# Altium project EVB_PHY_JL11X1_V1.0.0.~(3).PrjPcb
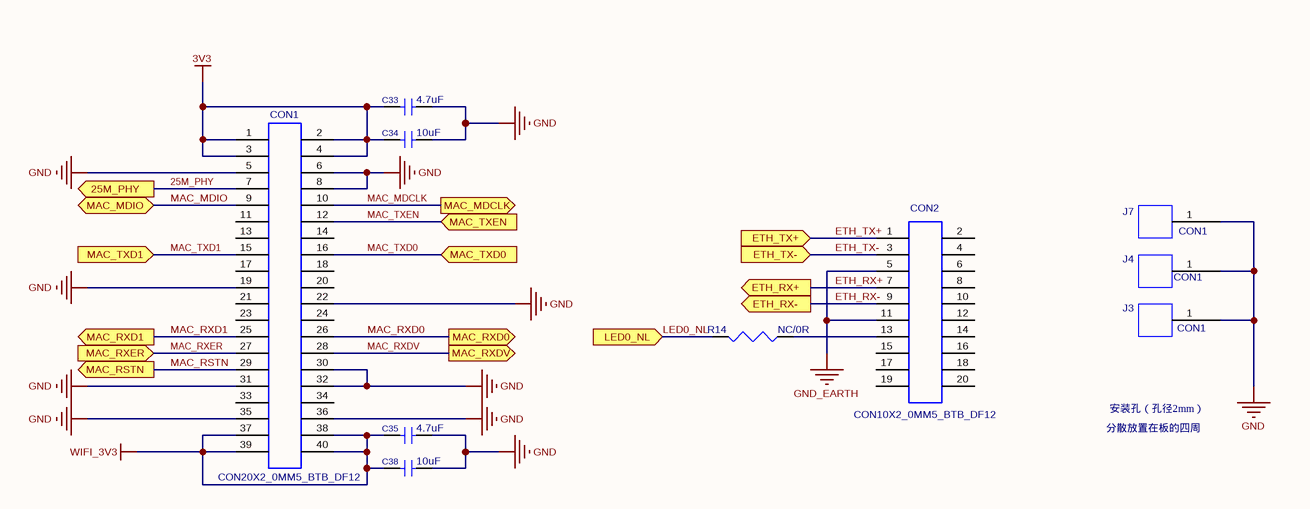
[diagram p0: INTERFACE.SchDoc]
3 sheets, 60 parts. Net scope: flat (ports and power ports of the same name join across sheets).
Sheets:
  INTERFACE.SchDoc
  JL11X1.SchDoc
  CHANGE_HISTORY.SchDoc

## Sheet INTERFACE.SchDoc: EVB_PHY_JL11x1_v1.0.0
size A4; Revision: V1.0.0; SheetNumber: 2; SheetTotal: 3; Release Date: 2014-05-28; SchModifyDate: 2020.11.1; PCBVersion: V1.0.0; PCBPartNumber: EVB_PHY_SZ18201; 版本号: V1.0.0

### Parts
C33  4.7uF  [C0603]
C34  10uF  [C0805]
C35  4.7uF  [C0603]
C38  10uF  [C0805]
CON1  CON20X2_0MM5_BTB_DF12  [CON20X2_0MM5_BTB_DF12_N]
CON2  CON10X2_0MM5_BTB_DF12  [CON10X2_0MM5_BTB_DF12_N]
J3  CON1  [H_2MM2_4MM]
J4  CON1  [H_2MM2_4MM]
J7  CON1  [H_2MM2_4MM]
R14  NC/0R  [R0603]

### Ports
25M_PHY (out), ETH_RX+ (out), ETH_RX- (out), ETH_TX+ (in), ETH_TX- (in), LED0_NL (in), MAC_MDCLK (out), MAC_MDIO (bidir), MAC_RSTN (out), MAC_RXD0 (out), MAC_RXD1 (out), MAC_RXDV (out), MAC_RXER (in), MAC_TXD0 (in), MAC_TXD1 (in), MAC_TXEN (in)

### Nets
3V3: C33.1 C34.1 CON1.1 CON1.2 CON1.3 CON1.4
GND: C33.2 C34.2 C35.2 C38.2 CON1.5 CON1.6 CON1.8 CON1.19 CON1.22 CON1.30 CON1.31 CON1.32 CON1.35 CON1.36 J3.1 J4.1 J7.1
GND_EARTH: CON2.5 CON2.11
WIFI_3V3: C35.1 C38.1 CON1.37 CON1.38 CON1.39 CON1.40
25M_PHY: CON1.7 ; port 25M_PHY
ETH_RX+: CON2.7 ; port ETH_RX+
ETH_RX-: CON2.9 ; port ETH_RX-
ETH_TX+: CON2.1 ; port ETH_TX+
ETH_TX-: CON2.3 ; port ETH_TX-
LED0_NL: R14.2 ; port LED0_NL
MAC_MDCLK: CON1.10 ; port MAC_MDCLK
MAC_MDIO: CON1.9 ; port MAC_MDIO
MAC_RSTN: CON1.29 ; port MAC_RSTN
MAC_RXD0: CON1.26 ; port MAC_RXD0
MAC_RXD1: CON1.25 ; port MAC_RXD1
MAC_RXDV: CON1.28 ; port MAC_RXDV
MAC_RXER: CON1.27 ; port MAC_RXER
MAC_TXD0: CON1.16 ; port MAC_TXD0
MAC_TXD1: CON1.15 ; port MAC_TXD1
MAC_TXEN: CON1.12 ; port MAC_TXEN
NetCON2_13: CON2.13 R14.1

Not connected (* = marked no-connect by the designer): CON1 11 13 14 17 18 20 21 23 24 33 34; CON2 2 4 6 8 10 12 14 15 16 17 18 19 20

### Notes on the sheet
- 分散放置在板的四周
- 安装孔（孔径2mm）

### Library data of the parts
C33 C35 = CC0304752XX: C/C,4.7uF,10V +/-10%,0603; Catalog: 陶瓷电容
C34 C38 = CC0501063XX: C/C,10uF,16V,+/-20%,0805; Catalog: 陶瓷电容
CON1 = CNBBM4000XX: 0.5mm ，BTB2*20Pin，SMT，公座，H3.0，DF12#(3.0)-40DS-0.5; PCB DECAL: CON20X2_0MM5_BTB_DF12_BOTTOM; Catalog: Connector
CON2 = CNBBM2000XX: 0.5mm ，BTB2*10Pin，SMT，公座，H3.0，DF12#(3.0)-20DS-0.5; PCB DECAL: CON10X2_0MM5_BTB_DF12_BOTTOM; Catalog: Connector
J3 J4 J7 = CON1: Source_Path: D:\CADENCE\SPB_16.3\TOOLS\CAPTURE\LIBRARY\CONNECTOR.OLB
R14 = CR0300000XX: Res,0R,1/10W,+/-5%,0603; Remark: NC; Catalog: 贴片电阻

## Sheet JL11X1.SchDoc: EVB_PHY_JL11x1_V1.0.0
size A4; Revision: V1.0.0; SheetNumber: 3; SheetTotal: 3; Release Date: 2014-05-28; SchModifyDate: 2020.11.1; PCBVersion: V1.0.0; PCBPartNumber: EVB_PHY_SZ18201; 版本号: V1.0.0
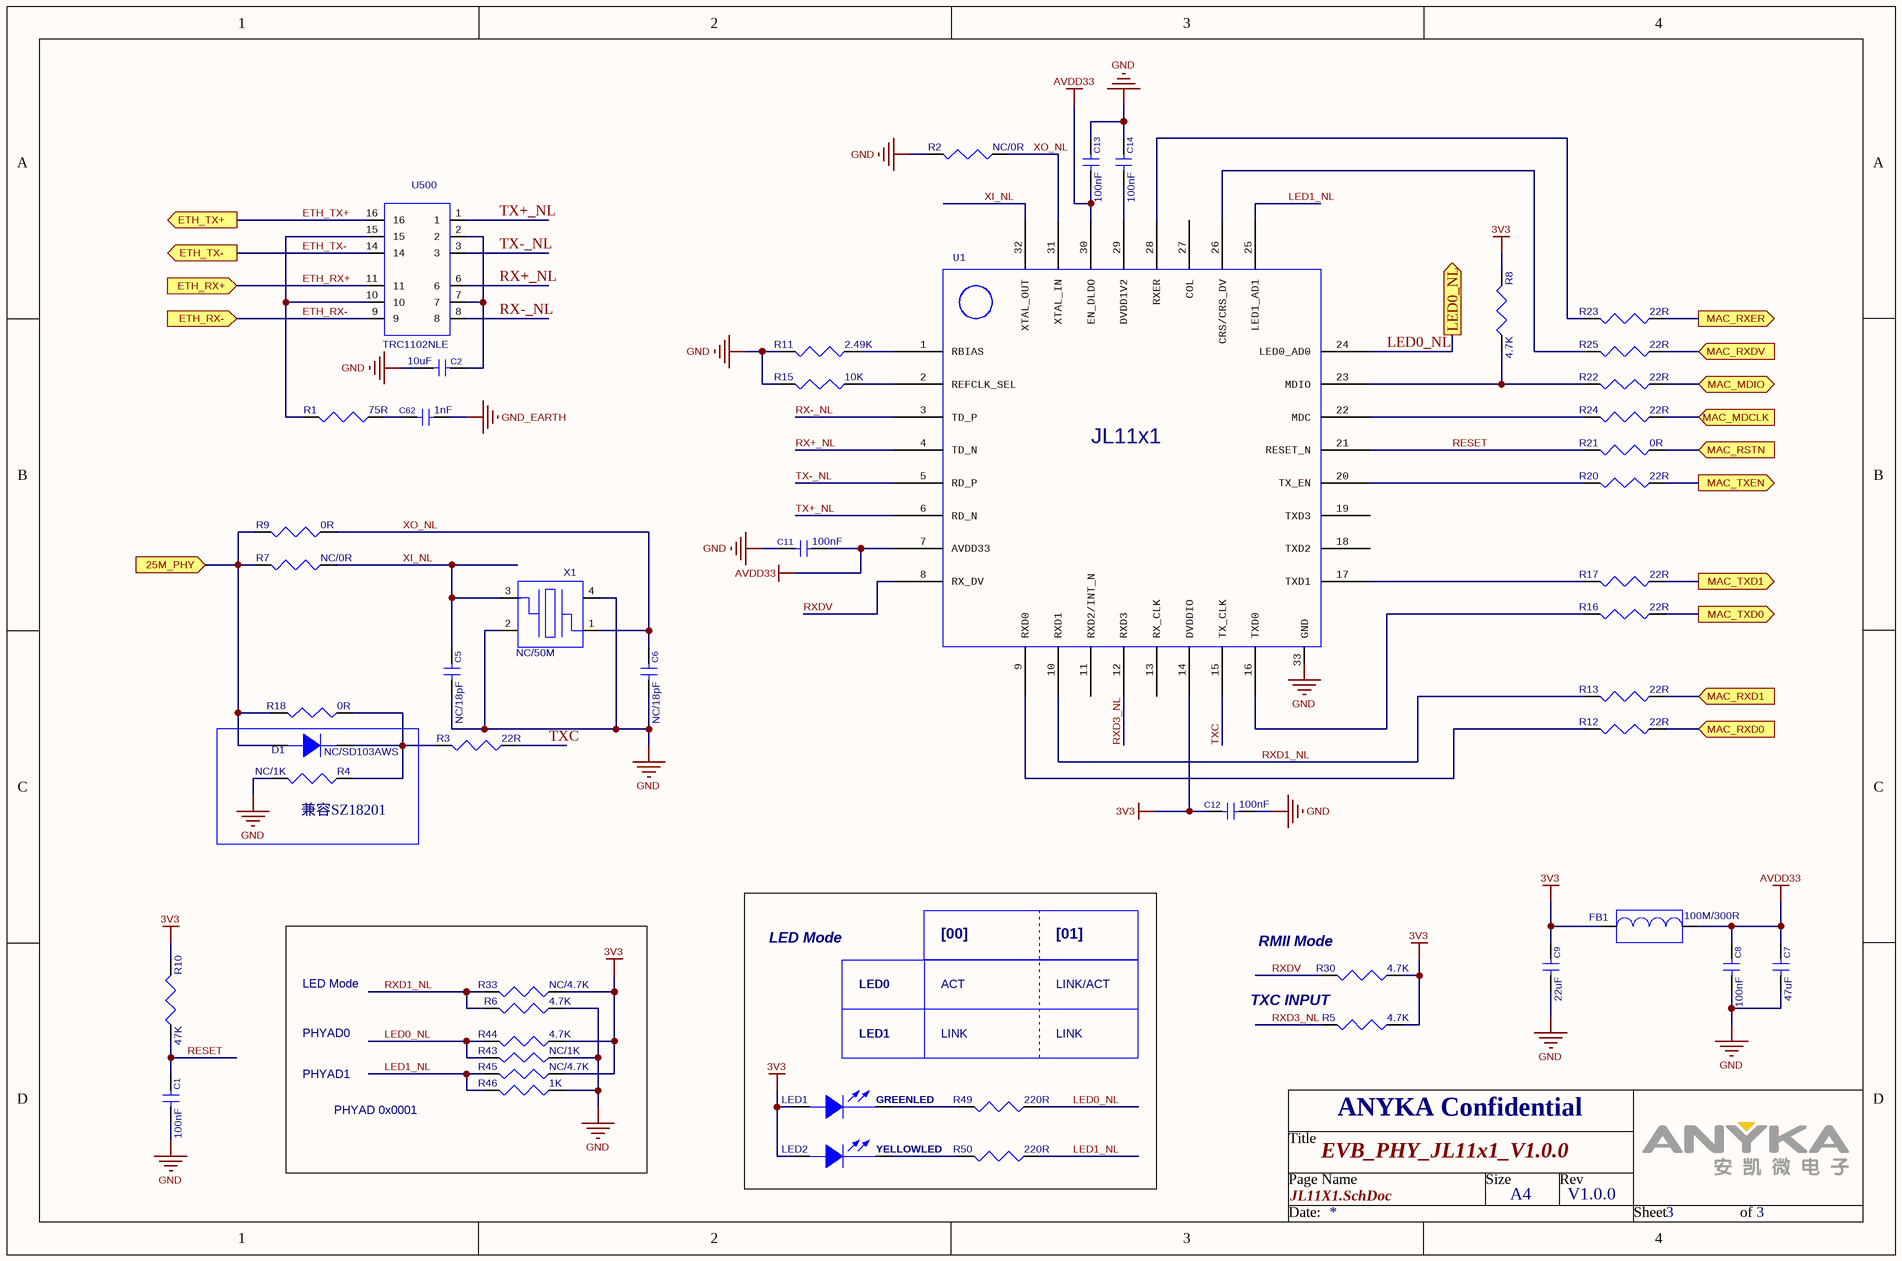
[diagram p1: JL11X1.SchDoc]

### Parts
C1  100nF  [C0603]
C2  10uF  [C0805]
C5  NC/18pF  [C0603]
C6  NC/18pF  [C0603]
C7  47uF  [C1210]
C8  100nF  [C0603]
C9  22uF  [C1210]
C11  100nF  [C0603]
C12  100nF  [C0603]
C13  100nF  [C0603]
C14  100nF  [C0603]
C62  1nF  [C1206]
D1  NC/SD103AWS  [SOD-323]
FB1  100M/300R  [FB0603]
LED1  GREENLED  [LED0603]
LED2  YELLOWLED  [LED0603]
R1  75R  [R0603]
R2  NC/0R  [R0603]
R3  22R  [R0603]
R4  NC/1K  [R0603]
R5  4.7K  [R0603]
R6  4.7K  [R0603]
R7  NC/0R  [R0603]
R8  4.7K  [R0603]
R9  0R  [R0603]
R10  47K  [R0603]
R11  2.49K  [R0603]
R12  22R  [R0603]
R13  22R  [R0603]
R15  10K  [R0603]
R16  22R  [R0603]
R17  22R  [R0603]
R18  0R  [R0603]
R20  22R  [R0603]
R21  0R  [R0603]
R22  22R  [R0603]
R23  22R  [R0603]
R24  22R  [R0603]
R25  22R  [R0603]
R30  4.7K  [R0603]
R33  NC/4.7K  [R0603]
R43  NC/1K  [R0603]
R44  4.7K  [R0603]
R45  NC/4.7K  [R0603]
R46  1K  [R0603]
R49  220R  [R0603]
R50  220R  [R0603]
U1  JL1101  [QFN32_0MM5_5X5MM]  (value not drawn)
U500  TRC1102NLE  [TRC1102NLE]
X1  value NC/50M  [KSX23]  (hidden comment: KSX23)

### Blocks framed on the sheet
兼容SZ18201: D1 R4

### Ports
25M_PHY (in), ETH_RX+ (in), ETH_RX- (in), ETH_TX+ (out), ETH_TX- (out), LED0_NL (out), MAC_MDCLK (in), MAC_MDIO (bidir), MAC_RSTN (in), MAC_RXD0 (in), MAC_RXD1 (in), MAC_RXDV (in), MAC_RXER (out), MAC_TXD0 (out), MAC_TXD1 (out), MAC_TXEN (out)

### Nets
3V3: C9.1 C12.1 FB1.1 LED1.A LED2.A R5.1 R8.2 R10.2 R30.1 R33.1 R44.1 R45.1 U1.14(DVDDIO)
AVDD33: C7.1 C8.1 C11.2 C13.2 FB1.2 U1.7(AVDD33) U1.30(EN_DLDO)
GND: C1.2 C2.2 C5.2 C6.2 C7.2 C8.2 C9.2 C11.1 C12.2 C13.1 C14.1 R2.2 R4.1 R6.1 R11.2 R15.2 R43.1 R46.1 U1.33(GND) X1.2 X1.4
GND_EARTH: C62.2
25M_PHY: D1.A R7.2 R9.2 R18.2 ; port 25M_PHY
ETH_RX+: U500.11 ; port ETH_RX+
ETH_RX-: U500.9 ; port ETH_RX-
ETH_TX+: U500.16 ; port ETH_TX+
ETH_TX-: U500.14 ; port ETH_TX-
LED0_NL: R43.2 R44.2 R49.1 U1.24(LED0_AD0) ; port LED0_NL
LED1_NL: R45.2 R46.2 R50.1 U1.25(LED1_AD1)
MAC_MDCLK: R24.1 ; port MAC_MDCLK
MAC_MDIO: R22.1 ; port MAC_MDIO
MAC_RSTN: R21.1 ; port MAC_RSTN
MAC_RXD0: R12.1 ; port MAC_RXD0
MAC_RXD1: R13.1 ; port MAC_RXD1
MAC_RXDV: R25.1 ; port MAC_RXDV
MAC_RXER: R23.1 ; port MAC_RXER
MAC_TXD0: R16.1 ; port MAC_TXD0
MAC_TXD1: R17.1 ; port MAC_TXD1
MAC_TXEN: R20.1 ; port MAC_TXEN
RESET: C1.1 R10.1 R21.2 U1.21(RESET_N)
RX+_NL: U1.4(TD_N) U500.6
RX-_NL: U1.3(TD_P) U500.8
RXD1_NL: R6.2 R13.2 R33.2 U1.10(RXD1)
RXD3_NL: R5.2 U1.12(RXD3)
RXDV: R30.2 U1.8(RX_DV)
TX+_NL: U1.6(RD_N) U500.1
TX-_NL: U1.5(RD_P) U500.3
TXC: R3.1 U1.15(TX_CLK)
XI_NL: C5.1 R7.1 U1.32(XTAL_OUT) X1.3
XO_NL: C6.1 R2.1 R9.1 U1.31(XTAL_IN) X1.1
NetC2_1: C2.1 U500.2 U500.7
NetC14_2: C14.2 U1.29(DVDD1V2)
NetC62_1: C62.1 R1.1
NetD1_K: D1.K R3.2 R4.2 R18.1
NetLED1_K: LED1.K R49.2
NetLED2_K: LED2.K R50.2
NetR1_2: R1.2 U500.10 U500.15
NetR8_1: R8.1 R22.2 U1.23(MDIO)
NetR11_1: R11.1 U1.1(RBIAS)
NetR12_2: R12.2 U1.9(RXD0)
NetR15_1: R15.1 U1.2(REFCLK_SEL)
NetR16_2: R16.2 U1.16(TXD0)
NetR17_2: R17.2 U1.17(TXD1)
NetR20_2: R20.2 U1.20(TX_EN)
NetR23_2: R23.2 U1.28(RXER)
NetR24_2: R24.2 U1.22(MDC)
NetR25_2: R25.2 U1.26(CRS/CRS_DV)

Not connected (* = marked no-connect by the designer): U1 11(RXD2/INT_N) 13(RX_CLK) 18(TXD2) 19(TXD3) 27(COL)

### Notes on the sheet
- LED Mode
- [00]
- [01]
- (near R30) RMII Mode
- PHYAD0
- (near LED1) LED1
- LED0
- LINK
- ACT
- LINK/ACT
- TXC INPUT
- PHYAD1
- PHYAD 0x0001

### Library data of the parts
C1 C8 C11-C14 = CC0301042XX: C/C,100nF,50V,+/-10%,0603; Catalog: 陶瓷电容
C2 = CC0501063XX: C/C,10uF,16V,+/-20%,0805; Catalog: 陶瓷电容
C5 C6 = CC0301800XX: C/C,18pF,25V,+/-5%,0603; Remark: NC; Catalog: 陶瓷电容
C7 = TC1004761XX: T/C,47uF,10V,+/-10%,1210; Catalog: 陶瓷电容
C9 = CC1002260XX: C/C,22uF,16V,+/-10%,1210; Catalog: 陶瓷电容
C62 = CC0601021XX: C/C,1nF,2KV,+/-10%,1206; Catalog: 陶瓷电容
D1 = DD32SCH07XX: Schottky Barrier Diodes,SD103AWS,SOD-323; PART_NUMBER: XXXXXXXX; PCB DECAL: 1N4148_SMD; Remark: NC; Catalog: 二极管
FB1 = BE0303011XX: BEAD,300R,100MHz,0603; SOURCE_PATH: D:\PROGRAM FILES\ORCAD\ORCAD_10.5\TOOLS\CAPTURE\LIBRARY\DISCRETE.OLB; Catalog: 贴片磁珠
LED1 = LE03GXX00XX: GREENLED,0603; Catalog: 二极管
LED2 = LE03YXX00XX: YELLOW,LED0603; Catalog: 二极管
R1 = CR0307500XX: Res,75R,1/10W,+/-5%,0603; Catalog: 贴片电阻
R2 R7 = CR0300000XX: as R14 on sheet INTERFACE
R3 R12 R13 R16 R17 R20 R22-R25 = CR0302200XX: Res,22R,1/10W,+/-5%,0603; Catalog: 贴片电阻
R4 R43 = CR0301020XX: Res,1K,1/10W,+/-5%,0603; Remark: NC; Catalog: 贴片电阻
R5 R6 R8 R30 R44 = CR0304720XX: Res,4.7K,1/10W,+/-5%,0603; Catalog: 贴片电阻
R9 R18 R21 = CR0300000XX: Res,0R,1/10W,+/-5%,0603; Catalog: 贴片电阻
R10 = CR0347020XX: Res,47K,1/10W,+/-1%,0603; Catalog: 贴片电阻
R11 = CR0324910XX: Res,2.49K,1/10W,+/-1%,0603; Catalog: 贴片电阻
R15 = CR0310020XX: Res,10K,1/10W,+/-1%,0603; Catalog: 贴片电阻
R33 R45 = CR0304720XX: Res,4.7K,1/10W,+/-5%,0603; Remark: NC; Catalog: 贴片电阻
R46 = CR0301020XX: Res,1K,1/10W,+/-5%,0603; Catalog: 贴片电阻
R49 R50 = CR0302211XX: Res,220R,1/10W,+/-1%,0603; Catalog: 贴片电阻
U1 = JCQFNPY05XX: Ethernet PHY,JL1101-N032C,QFN32,JLSemi; PCB DECAL: RTL8201F_QFN32_0MM5_5X5MM; Source_Path: F:\WORK_SPACE\ERIC\RTL8201\RTL8201F\SCHEMATIC\QFN32_RMII_MII\REFERENCE\V1.4\RTL8201F(E)_COLAY_REFERENCE_1.4.DSN; Value: RTL8201F-CG; Catalog: 集成电路
U500 = TFSMD1601XX: Transformer,Trxcom,TRC1188NL,16pin; Part_RNEfNErNEncNE: NU704; room: ethernet; NC: 4,5,12,13; Source_Path: D:\MOBILE_PROJECT\WINCE\WINCE-7802\LIBRARY1.OLB; Catalog: 网络变压器
X1 = KSX23: Source_Path: L:\PCB_DESIGN_SYSTEM\ALLEGRO\LIB\SCHEMATIC\MISC.OLB

## Sheet CHANGE_HISTORY.SchDoc: EVB_PHY_JL11x1_V1.0.0
size A4; Revision: V1.0.0; SheetNumber: 1; SheetTotal: 3; Release Date: 2014-05-28; SchModifyDate: 2020.11.1; PCBVersion: V1.0.0; PCBPartNumber: EVB_PHY_SZ18201; 版本号: V1.0.0
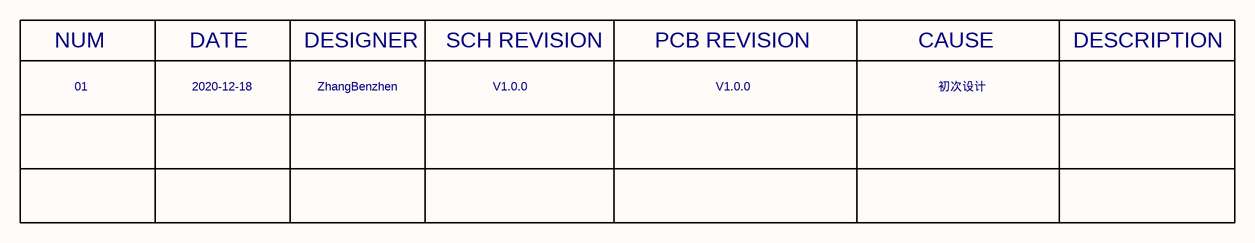
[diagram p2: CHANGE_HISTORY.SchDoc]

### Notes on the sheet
- NUM
- DATE
- DESIGNER
- SCH REVISION
- PCB REVISION
- CAUSE
- DESCRIPTION
- 01
- 2020-12-18
- ZhangBenzhen
- V1.0.0
- 初次设计

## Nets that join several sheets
3V3: INTERFACE (6 pins), JL11X1 (13 pins)
GND: INTERFACE (17 pins), JL11X1 (21 pins)
GND_EARTH: INTERFACE (CON2.5 CON2.11), JL11X1 (C62.2)
25M_PHY: INTERFACE (CON1.7), JL11X1 (D1.A R7.2 R9.2 R18.2)
ETH_RX+: INTERFACE (CON2.7), JL11X1 (U500.11)
ETH_RX-: INTERFACE (CON2.9), JL11X1 (U500.9)
ETH_TX+: INTERFACE (CON2.1), JL11X1 (U500.16)
ETH_TX-: INTERFACE (CON2.3), JL11X1 (U500.14)
LED0_NL: INTERFACE (R14.2), JL11X1 (R43.2 R44.2 R49.1 U1.24)
MAC_MDCLK: INTERFACE (CON1.10), JL11X1 (R24.1)
MAC_MDIO: INTERFACE (CON1.9), JL11X1 (R22.1)
MAC_RSTN: INTERFACE (CON1.29), JL11X1 (R21.1)
MAC_RXD0: INTERFACE (CON1.26), JL11X1 (R12.1)
MAC_RXD1: INTERFACE (CON1.25), JL11X1 (R13.1)
MAC_RXDV: INTERFACE (CON1.28), JL11X1 (R25.1)
MAC_RXER: INTERFACE (CON1.27), JL11X1 (R23.1)
MAC_TXD0: INTERFACE (CON1.16), JL11X1 (R16.1)
MAC_TXD1: INTERFACE (CON1.15), JL11X1 (R17.1)
MAC_TXEN: INTERFACE (CON1.12), JL11X1 (R20.1)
